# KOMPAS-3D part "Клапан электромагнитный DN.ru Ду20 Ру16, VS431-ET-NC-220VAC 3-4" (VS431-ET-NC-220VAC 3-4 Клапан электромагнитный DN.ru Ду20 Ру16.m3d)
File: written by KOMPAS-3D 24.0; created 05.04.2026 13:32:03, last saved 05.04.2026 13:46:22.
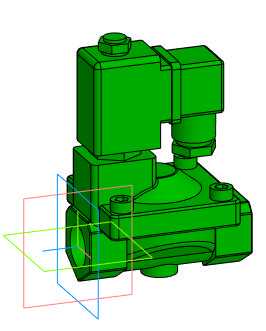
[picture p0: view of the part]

Document properties: Автор: artio; Полное имя файла: C:\Users\artio\OneDrive\Рабочий стол\Клапан электромагнитный DN.ru\VS431\VS431-ET-NC\VS431-ET-NC-220VAC\Ду20\VS431-ET-NC-220VAC 3-4 Клапан электромагнитный DN.ru Ду20 Ру16.m3d

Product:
- Body: Тело 1  | qty 1
    Масса: 1.198355
- Part/product: Клапан электромагнитный DN.ru Ду20 Ру16  | designation VS431-ET-NC-220VAC 3-4
    Масса: 0.907
    Раздел спецификации: Прочие изделия
    Примечание: D130-04706
    additional columns: ef56311e-7521-43dc-8291-0e6108b3d81d; artio; c; Шероховатость не задана; Да

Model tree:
1. Операция без истории:1

Expressions: VS431-ET-NC-220VAC 3-4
